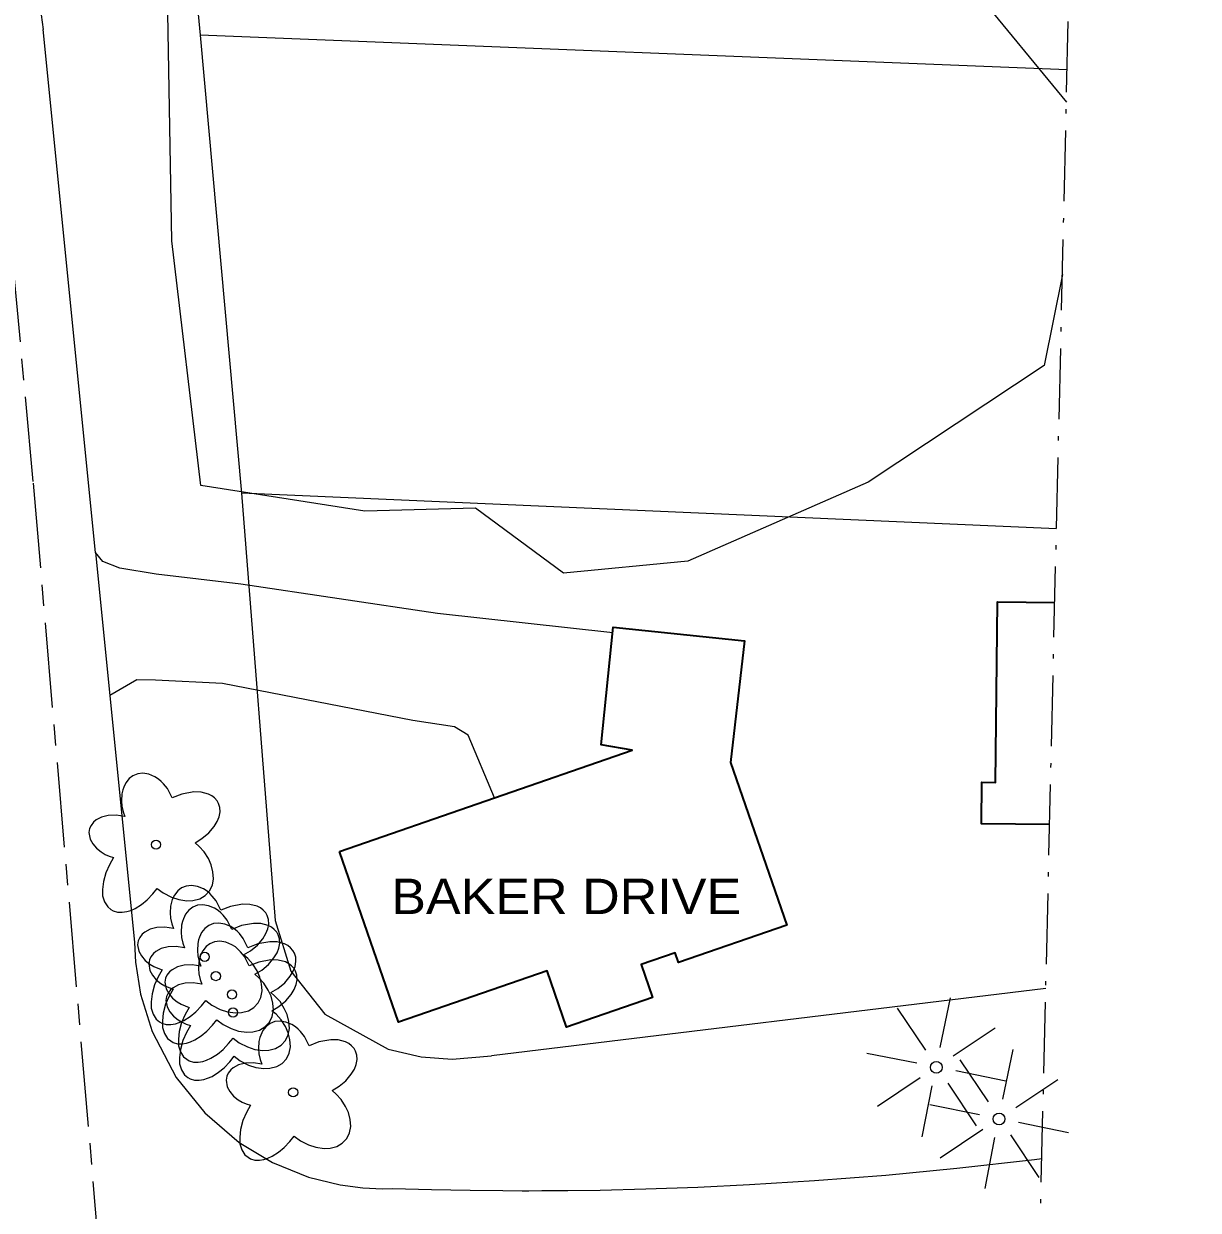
# Model space of a CAD drawing. Extents: x -861682 to -858969, y -1797841 to -1795153.
# Drawn here: x -859173.6 to -858974.4, y -1796344.2 to -1796143 of the extents above; entities that cross this region are included whole.
import ezdxf

# ---------------------------------------------------------------- set-up
doc = ezdxf.new("R2010")
doc.units = 0
doc.header["$LTSCALE"] = 2.4
doc.linetypes.add('DOT_DASHED', pattern=[7.7, 5, -1.2, 0.3, -1.2])
doc.linetypes.add('LONG_DASH_SHORT_DASH', pattern=[9.9, 6, -1.2, 1.5, -1.2])
for name, color, linetype, lineweight in [('10', 7, 'Continuous', 25), ('11', 7, 'Continuous', 13), ('12', 7, 'Continuous', 35), ('17', 7, 'Continuous', 13), ('18', 7, 'Continuous', 13), ('30', 7, 'Continuous', 13), ('32', 7, 'LONG_DASH_SHORT_DASH', 13), ('42', 7, 'Continuous', 25), ('46', 7, 'Continuous', 13), ('61', 7, 'Continuous', 13)]:
    doc.layers.add(name, color=color, linetype=linetype, lineweight=lineweight)

msp = doc.modelspace()

# ---------------------------------------------------------------- linework, layer by layer
at = {"layer": '10'}
for p, q in [((-859161.47, -1796232.698), (-859170.355, -1796144.002)), ((-859161.47, -1796232.698), (-859159.043, -1796256.938)), ((-859159.043, -1796256.938), (-859154.849, -1796298.818))]:
    msp.add_line(p, q, dxfattribs=at)
for points in [[(-859180.121, -1796063.829), (-859178.218, -1796080.987), (-859171.015, -1796139.046), (-859170.355, -1796144.002)], [(-859154.849, -1796298.818), (-859154.675, -1796302.118), (-859153.815, -1796307.556), (-859151.861, -1796313.866), (-859147.776, -1796321.661), (-859142.944, -1796327.66), (-859137.104, -1796332.683), (-859131.441, -1796336.084), (-859125.319, -1796338.563), (-859119.972, -1796339.878), (-859116.105, -1796340.384), (-859112.803, -1796340.532), (-859111.109, -1796340.507)], [(-859111.109, -1796340.507), (-859104.5, -1796340.688), (-859097.889, -1796340.807), (-859092.379, -1796340.859), (-859089.073, -1796340.869), (-859087.971, -1796340.869), (-859085.767, -1796340.864), (-859081.359, -1796340.832), (-859075.85, -1796340.755), (-859068.138, -1796340.573), (-859059.328, -1796340.263), (-859050.522, -1796339.842), (-859039.523, -1796339.161), (-859027.438, -1796338.213), (-859015.372, -1796337.057), (-859002.233, -1796335.559), (-859000.959, -1796335.391)]]:
    msp.add_lwpolyline(points, dxfattribs=at)
at = {"layer": '11'}
for points in [[(-859073.737, -1796246.291), (-859103.483, -1796243.036), (-859136.793, -1796238.058), (-859151.172, -1796236.33), (-859157.333, -1796235.314), (-859160.187, -1796234.203), (-859161.47, -1796232.698)], [(-859093.814, -1796274.266), (-859098.255, -1796263.641), (-859100.565, -1796262.245), (-859107.636, -1796261.142), (-859139.924, -1796254.887), (-859151.276, -1796254.315), (-859154.469, -1796254.239), (-859159.043, -1796256.938)]]:
    msp.add_lwpolyline(points, dxfattribs=at)
at = {"layer": '12'}
msp.add_lwpolyline([(-858999.641, -1796278.809), (-859011.206, -1796278.682), (-859011.128, -1796271.62), (-859008.796, -1796271.646), (-859008.455, -1796241.055), (-858998.765, -1796241.163)], dxfattribs=at)
msp.add_lwpolyline([(-859120.065, -1796283.342), (-859070.464, -1796266.193), (-859075.682, -1796265.265), (-859073.641, -1796245.352), (-859051.384, -1796247.633), (-859053.765, -1796268.256), (-859044.226, -1796295.846), (-859062.594, -1796302.197), (-859063.165, -1796300.545), (-859068.938, -1796302.54), (-859067.011, -1796308.115), (-859081.555, -1796313.142), (-859084.848, -1796303.616), (-859110.046, -1796312.326)], close=True, dxfattribs=at)
at = {"layer": '17'}
for p, q in [((-859018.2, -1796316.6), (-859016.474, -1796308.2)), ((-859020.66, -1796317.06), (-859025.45, -1796309.932)), ((-859016, -1796318), (-859008.904, -1796313.26)), ((-859022.16, -1796319.26), (-859030.622, -1796317.586)), ((-859007.558, -1796325.355), (-859005.832, -1796316.955)), ((-859010.018, -1796325.815), (-859014.808, -1796318.687)), ((-859021.62, -1796321.76), (-859028.846, -1796326.616)), ((-859015.56, -1796320.52), (-859007.08, -1796322.244)), ((-859005.358, -1796326.755), (-858998.262, -1796322.015)), ((-859021.24, -1796331.72), (-859019.56, -1796323.12)), ((-859016.9, -1796322.66), (-859012.1, -1796329.874)), ((-859011.518, -1796328.015), (-859019.98, -1796326.341)), ((-859004.918, -1796329.275), (-858996.438, -1796330.999)), ((-859010.978, -1796330.515), (-859018.204, -1796335.371)), ((-859010.598, -1796340.475), (-859008.918, -1796331.875)), ((-859006.258, -1796331.415), (-859001.458, -1796338.629))]:
    msp.add_line(p, q, dxfattribs=at)
for points in [[(-859151.011, -1796289.617), (-859149.969, -1796290.385), (-859148.563, -1796291.107), (-859147.315, -1796291.513), (-859145.943, -1796291.709), (-859144.925, -1796291.659), (-859143.781, -1796291.369), (-859142.849, -1796290.817), (-859142.109, -1796290.029), (-859141.641, -1796289.071), (-859141.431, -1796287.993), (-859141.535, -1796286.797), (-859141.825, -1796285.625), (-859142.311, -1796284.565), (-859143.033, -1796283.421), (-859143.899, -1796282.501), (-859144.581, -1796281.889), (-859143.399, -1796281.173), (-859142.253, -1796280.225), (-859141.333, -1796279.133), (-859140.811, -1796278.277), (-859140.479, -1796277.463), (-859140.333, -1796276.647), (-859140.373, -1796275.885), (-859140.589, -1796275.205), (-859140.847, -1796274.753), (-859141.267, -1796274.279), (-859141.727, -1796273.925), (-859142.293, -1796273.635), (-859143.529, -1796273.307), (-859144.771, -1796273.273), (-859146.817, -1796273.649), (-859148.477, -1796274.287), (-859149.267, -1796272.709), (-859149.921, -1796271.895), (-859150.333, -1796271.493), (-859150.797, -1796271.093), (-859151.399, -1796270.701), (-859152.403, -1796270.269), (-859153.417, -1796270.099), (-859154.305, -1796270.199), (-859155.105, -1796270.533), (-859155.771, -1796271.019), (-859156.331, -1796271.725), (-859156.681, -1796272.481), (-859156.839, -1796272.919), (-859157.007, -1796273.595), (-859157.059, -1796274.757), (-859156.987, -1796275.655), (-859156.775, -1796276.617), (-859156.491, -1796277.423), (-859157.933, -1796277.191), (-859159.291, -1796277.241), (-859160.449, -1796277.527), (-859161.337, -1796278.025), (-859161.777, -1796278.369), (-859162.211, -1796278.935), (-859162.449, -1796279.469), (-859162.573, -1796280.147), (-859162.371, -1796281.251), (-859161.915, -1796282.063), (-859161.291, -1796282.825), (-859160.513, -1796283.441), (-859159.815, -1796283.865), (-859159.151, -1796284.153), (-859158.423, -1796284.391), (-859159.107, -1796285.603), (-859159.729, -1796286.971), (-859160.125, -1796288.473), (-859160.259, -1796289.807), (-859160.249, -1796290.897), (-859159.915, -1796291.915), (-859159.393, -1796292.761), (-859158.835, -1796293.197), (-859158.449, -1796293.443), (-859157.715, -1796293.667), (-859156.921, -1796293.679), (-859156.151, -1796293.555), (-859155.491, -1796293.343), (-859154.747, -1796293.021), (-859153.671, -1796292.341), (-859152.709, -1796291.555), (-859151.753, -1796290.537), (-859151.007, -1796289.627)], [(-859142.762, -1796308.637), (-859141.72, -1796309.405), (-859140.314, -1796310.127), (-859139.066, -1796310.533), (-859137.694, -1796310.729), (-859136.676, -1796310.679), (-859135.532, -1796310.389), (-859134.6, -1796309.837), (-859133.86, -1796309.049), (-859133.392, -1796308.091), (-859133.182, -1796307.013), (-859133.286, -1796305.817), (-859133.576, -1796304.645), (-859134.062, -1796303.585), (-859134.784, -1796302.441), (-859135.65, -1796301.521), (-859136.332, -1796300.909), (-859135.15, -1796300.193), (-859134.004, -1796299.245), (-859133.084, -1796298.153), (-859132.562, -1796297.297), (-859132.23, -1796296.483), (-859132.084, -1796295.667), (-859132.124, -1796294.905), (-859132.34, -1796294.225), (-859132.598, -1796293.773), (-859133.018, -1796293.299), (-859133.478, -1796292.945), (-859134.044, -1796292.655), (-859135.28, -1796292.327), (-859136.522, -1796292.293), (-859138.568, -1796292.669), (-859140.228, -1796293.307), (-859141.018, -1796291.729), (-859141.672, -1796290.915), (-859142.084, -1796290.513), (-859142.548, -1796290.113), (-859143.15, -1796289.721), (-859144.154, -1796289.289), (-859145.168, -1796289.119), (-859146.056, -1796289.219), (-859146.856, -1796289.553), (-859147.522, -1796290.039), (-859148.082, -1796290.745), (-859148.432, -1796291.501), (-859148.59, -1796291.939), (-859148.758, -1796292.615), (-859148.81, -1796293.777), (-859148.738, -1796294.675), (-859148.526, -1796295.637), (-859148.242, -1796296.443), (-859149.684, -1796296.211), (-859151.042, -1796296.261), (-859152.2, -1796296.547), (-859153.088, -1796297.045), (-859153.528, -1796297.389), (-859153.962, -1796297.955), (-859154.2, -1796298.489), (-859154.324, -1796299.167), (-859154.122, -1796300.271), (-859153.666, -1796301.083), (-859153.042, -1796301.845), (-859152.264, -1796302.461), (-859151.566, -1796302.885), (-859150.902, -1796303.173), (-859150.174, -1796303.411), (-859150.858, -1796304.623), (-859151.48, -1796305.991), (-859151.876, -1796307.493), (-859152.01, -1796308.827), (-859152, -1796309.917), (-859151.666, -1796310.935), (-859151.144, -1796311.781), (-859150.586, -1796312.217), (-859150.2, -1796312.463), (-859149.466, -1796312.687), (-859148.672, -1796312.699), (-859147.902, -1796312.575), (-859147.242, -1796312.363), (-859146.498, -1796312.041), (-859145.422, -1796311.361), (-859144.46, -1796310.575), (-859143.504, -1796309.557), (-859142.758, -1796308.647)], [(-859140.874, -1796311.906), (-859139.832, -1796312.674), (-859138.426, -1796313.396), (-859137.178, -1796313.802), (-859135.806, -1796313.998), (-859134.788, -1796313.948), (-859133.644, -1796313.658), (-859132.712, -1796313.106), (-859131.972, -1796312.318), (-859131.504, -1796311.36), (-859131.294, -1796310.282), (-859131.398, -1796309.086), (-859131.688, -1796307.914), (-859132.174, -1796306.854), (-859132.896, -1796305.71), (-859133.762, -1796304.79), (-859134.444, -1796304.178), (-859133.262, -1796303.462), (-859132.116, -1796302.514), (-859131.196, -1796301.422), (-859130.674, -1796300.566), (-859130.342, -1796299.752), (-859130.196, -1796298.936), (-859130.236, -1796298.174), (-859130.452, -1796297.494), (-859130.71, -1796297.042), (-859131.13, -1796296.568), (-859131.59, -1796296.214), (-859132.156, -1796295.924), (-859133.392, -1796295.596), (-859134.634, -1796295.562), (-859136.68, -1796295.938), (-859138.34, -1796296.576), (-859139.13, -1796294.998), (-859139.784, -1796294.184), (-859140.196, -1796293.782), (-859140.66, -1796293.382), (-859141.262, -1796292.99), (-859142.266, -1796292.558), (-859143.28, -1796292.388), (-859144.168, -1796292.488), (-859144.968, -1796292.822), (-859145.634, -1796293.308), (-859146.194, -1796294.014), (-859146.544, -1796294.77), (-859146.702, -1796295.208), (-859146.87, -1796295.884), (-859146.922, -1796297.046), (-859146.85, -1796297.944), (-859146.638, -1796298.906), (-859146.354, -1796299.712), (-859147.796, -1796299.48), (-859149.154, -1796299.53), (-859150.312, -1796299.816), (-859151.2, -1796300.314), (-859151.64, -1796300.658), (-859152.074, -1796301.224), (-859152.312, -1796301.758), (-859152.436, -1796302.436), (-859152.234, -1796303.54), (-859151.778, -1796304.352), (-859151.154, -1796305.114), (-859150.376, -1796305.73), (-859149.678, -1796306.154), (-859149.014, -1796306.442), (-859148.286, -1796306.68), (-859148.97, -1796307.892), (-859149.592, -1796309.26), (-859149.988, -1796310.762), (-859150.122, -1796312.096), (-859150.112, -1796313.186), (-859149.778, -1796314.204), (-859149.256, -1796315.05), (-859148.698, -1796315.486), (-859148.312, -1796315.732), (-859147.578, -1796315.956), (-859146.784, -1796315.968), (-859146.014, -1796315.844), (-859145.354, -1796315.632), (-859144.61, -1796315.31), (-859143.534, -1796314.63), (-859142.572, -1796313.844), (-859141.616, -1796312.826), (-859140.87, -1796311.916)], [(-859138.134, -1796315.013), (-859137.092, -1796315.781), (-859135.686, -1796316.503), (-859134.438, -1796316.909), (-859133.066, -1796317.105), (-859132.048, -1796317.055), (-859130.904, -1796316.765), (-859129.972, -1796316.213), (-859129.232, -1796315.425), (-859128.764, -1796314.467), (-859128.554, -1796313.389), (-859128.658, -1796312.193), (-859128.948, -1796311.021), (-859129.434, -1796309.961), (-859130.156, -1796308.817), (-859131.022, -1796307.897), (-859131.704, -1796307.285), (-859130.522, -1796306.569), (-859129.376, -1796305.621), (-859128.456, -1796304.529), (-859127.934, -1796303.673), (-859127.602, -1796302.859), (-859127.456, -1796302.043), (-859127.496, -1796301.281), (-859127.712, -1796300.601), (-859127.97, -1796300.149), (-859128.39, -1796299.675), (-859128.85, -1796299.321), (-859129.416, -1796299.031), (-859130.652, -1796298.703), (-859131.894, -1796298.669), (-859133.94, -1796299.045), (-859135.6, -1796299.683), (-859136.39, -1796298.105), (-859137.044, -1796297.291), (-859137.456, -1796296.889), (-859137.92, -1796296.489), (-859138.522, -1796296.097), (-859139.526, -1796295.665), (-859140.54, -1796295.495), (-859141.428, -1796295.595), (-859142.228, -1796295.929), (-859142.894, -1796296.415), (-859143.454, -1796297.121), (-859143.804, -1796297.877), (-859143.962, -1796298.315), (-859144.13, -1796298.991), (-859144.182, -1796300.153), (-859144.11, -1796301.051), (-859143.898, -1796302.013), (-859143.614, -1796302.819), (-859145.056, -1796302.587), (-859146.414, -1796302.637), (-859147.572, -1796302.923), (-859148.46, -1796303.421), (-859148.9, -1796303.765), (-859149.334, -1796304.331), (-859149.572, -1796304.865), (-859149.696, -1796305.543), (-859149.494, -1796306.647), (-859149.038, -1796307.459), (-859148.414, -1796308.221), (-859147.636, -1796308.837), (-859146.938, -1796309.261), (-859146.274, -1796309.549), (-859145.546, -1796309.787), (-859146.23, -1796310.999), (-859146.852, -1796312.367), (-859147.248, -1796313.869), (-859147.382, -1796315.203), (-859147.372, -1796316.293), (-859147.038, -1796317.311), (-859146.516, -1796318.157), (-859145.958, -1796318.593), (-859145.572, -1796318.839), (-859144.838, -1796319.063), (-859144.044, -1796319.075), (-859143.274, -1796318.951), (-859142.614, -1796318.739), (-859141.87, -1796318.417), (-859140.794, -1796317.737), (-859139.832, -1796316.951), (-859138.876, -1796315.933), (-859138.13, -1796315.023)], [(-859137.956, -1796318.08), (-859136.914, -1796318.848), (-859135.508, -1796319.57), (-859134.26, -1796319.976), (-859132.888, -1796320.172), (-859131.87, -1796320.122), (-859130.726, -1796319.832), (-859129.794, -1796319.28), (-859129.054, -1796318.492), (-859128.586, -1796317.534), (-859128.376, -1796316.456), (-859128.48, -1796315.26), (-859128.77, -1796314.088), (-859129.256, -1796313.028), (-859129.978, -1796311.884), (-859130.844, -1796310.964), (-859131.526, -1796310.352), (-859130.344, -1796309.636), (-859129.198, -1796308.688), (-859128.278, -1796307.596), (-859127.756, -1796306.74), (-859127.424, -1796305.926), (-859127.278, -1796305.11), (-859127.318, -1796304.348), (-859127.534, -1796303.668), (-859127.792, -1796303.216), (-859128.212, -1796302.742), (-859128.672, -1796302.388), (-859129.238, -1796302.098), (-859130.474, -1796301.77), (-859131.716, -1796301.736), (-859133.762, -1796302.112), (-859135.422, -1796302.75), (-859136.212, -1796301.172), (-859136.866, -1796300.358), (-859137.278, -1796299.956), (-859137.742, -1796299.556), (-859138.344, -1796299.164), (-859139.348, -1796298.732), (-859140.362, -1796298.562), (-859141.25, -1796298.662), (-859142.05, -1796298.996), (-859142.716, -1796299.482), (-859143.276, -1796300.188), (-859143.626, -1796300.944), (-859143.784, -1796301.382), (-859143.952, -1796302.058), (-859144.004, -1796303.22), (-859143.932, -1796304.118), (-859143.72, -1796305.08), (-859143.436, -1796305.886), (-859144.878, -1796305.654), (-859146.236, -1796305.704), (-859147.394, -1796305.99), (-859148.282, -1796306.488), (-859148.722, -1796306.832), (-859149.156, -1796307.398), (-859149.394, -1796307.932), (-859149.518, -1796308.61), (-859149.316, -1796309.714), (-859148.86, -1796310.526), (-859148.236, -1796311.288), (-859147.458, -1796311.904), (-859146.76, -1796312.328), (-859146.096, -1796312.616), (-859145.368, -1796312.854), (-859146.052, -1796314.066), (-859146.674, -1796315.434), (-859147.07, -1796316.936), (-859147.204, -1796318.27), (-859147.194, -1796319.36), (-859146.86, -1796320.378), (-859146.338, -1796321.224), (-859145.78, -1796321.66), (-859145.394, -1796321.906), (-859144.66, -1796322.13), (-859143.866, -1796322.142), (-859143.096, -1796322.018), (-859142.436, -1796321.806), (-859141.692, -1796321.484), (-859140.616, -1796320.804), (-859139.654, -1796320.018), (-859138.698, -1796319), (-859137.952, -1796318.09)], [(-859127.76, -1796331.623), (-859126.718, -1796332.391), (-859125.312, -1796333.113), (-859124.064, -1796333.519), (-859122.692, -1796333.715), (-859121.674, -1796333.665), (-859120.53, -1796333.375), (-859119.598, -1796332.823), (-859118.858, -1796332.035), (-859118.39, -1796331.077), (-859118.18, -1796329.999), (-859118.284, -1796328.803), (-859118.574, -1796327.631), (-859119.06, -1796326.571), (-859119.782, -1796325.427), (-859120.648, -1796324.507), (-859121.33, -1796323.895), (-859120.148, -1796323.179), (-859119.002, -1796322.231), (-859118.082, -1796321.139), (-859117.56, -1796320.283), (-859117.228, -1796319.469), (-859117.082, -1796318.653), (-859117.122, -1796317.891), (-859117.338, -1796317.211), (-859117.596, -1796316.759), (-859118.016, -1796316.285), (-859118.476, -1796315.931), (-859119.042, -1796315.641), (-859120.278, -1796315.313), (-859121.52, -1796315.279), (-859123.566, -1796315.655), (-859125.226, -1796316.293), (-859126.016, -1796314.715), (-859126.67, -1796313.901), (-859127.082, -1796313.499), (-859127.546, -1796313.099), (-859128.148, -1796312.707), (-859129.152, -1796312.275), (-859130.166, -1796312.105), (-859131.054, -1796312.205), (-859131.854, -1796312.539), (-859132.52, -1796313.025), (-859133.08, -1796313.731), (-859133.43, -1796314.487), (-859133.588, -1796314.925), (-859133.756, -1796315.601), (-859133.808, -1796316.763), (-859133.736, -1796317.661), (-859133.524, -1796318.623), (-859133.24, -1796319.429), (-859134.682, -1796319.197), (-859136.04, -1796319.247), (-859137.198, -1796319.533), (-859138.086, -1796320.031), (-859138.526, -1796320.375), (-859138.96, -1796320.941), (-859139.198, -1796321.475), (-859139.322, -1796322.153), (-859139.12, -1796323.257), (-859138.664, -1796324.069), (-859138.04, -1796324.831), (-859137.262, -1796325.447), (-859136.564, -1796325.871), (-859135.9, -1796326.159), (-859135.172, -1796326.397), (-859135.856, -1796327.609), (-859136.478, -1796328.977), (-859136.874, -1796330.479), (-859137.008, -1796331.813), (-859136.998, -1796332.903), (-859136.664, -1796333.921), (-859136.142, -1796334.767), (-859135.584, -1796335.203), (-859135.198, -1796335.449), (-859134.464, -1796335.673), (-859133.67, -1796335.685), (-859132.9, -1796335.561), (-859132.24, -1796335.349), (-859131.496, -1796335.027), (-859130.42, -1796334.347), (-859129.458, -1796333.561), (-859128.502, -1796332.543), (-859127.756, -1796331.633)]]:
    msp.add_lwpolyline(points, dxfattribs=at)
for centre, radius in [((-859151.191, -1796282.205), 0.773), ((-859142.942, -1796301.225), 0.773), ((-859141.054, -1796304.494), 0.773), ((-859138.314, -1796307.601), 0.773), ((-859138.136, -1796310.668), 0.773), ((-859018.86, -1796319.96), 1), ((-859127.94, -1796324.211), 0.773), ((-859008.218, -1796328.715), 1)]:
    msp.add_circle(centre, radius, dxfattribs=at)
at = {"layer": '18'}
msp.add_line((-858997.47, -1796185.563), (-859000.584, -1796200.948), dxfattribs=at)
msp.add_lwpolyline([(-859000.584, -1796200.948), (-859030.413, -1796220.763), (-859061.004, -1796234.175), (-859082.06, -1796236.181), (-859097.001, -1796225.145), (-859115.759, -1796225.664), (-859143.622, -1796221.311), (-859148.513, -1796179.853), (-859149.493, -1796125.159), (-859163.095, -1796083.032), (-859153.599, -1796072.325), (-859106.129, -1796073.572), (-859073.857, -1796095.639), (-859070.132, -1796112.997), (-859043.544, -1796120.651), (-859012.341, -1796137.386), (-858996.789, -1796156.325)], dxfattribs=at)
at = {"layer": '30'}
for p, q in [((-858996.661, -1796150.826), (-859143.732, -1796144.99)), ((-858998.474, -1796228.675), (-859136.702, -1796222.627))]:
    msp.add_line(p, q, dxfattribs=at)
at = {"layer": '32'}
msp.add_lwpolyline([(-859608.727, -1795645.905), (-859547.475, -1795663.972), (-859512.218, -1795672.548), (-859448.852, -1795685.888), (-859390.25, -1795702.087), (-859346.418, -1795718.286), (-859312.114, -1795735.914), (-859284.005, -1795754.971), (-859271.617, -1795770.217), (-859251.13, -1795810.238), (-859242.554, -1795833.584), (-859228.738, -1795871.699), (-859218.732, -1795901.238), (-859209.68, -1795935.065), (-859202.057, -1795970.321), (-859196.34, -1796004.625), (-859192.528, -1796042.264), (-859177.759, -1796158.991), (-859172.04, -1796220.929), (-859156.019, -1796407.84)], dxfattribs=at)
at = {"layer": '42'}
msp.add_line((-859000.289, -1796306.601), (-859094.272, -1796318.009), dxfattribs=at)
for points in [[(-859152.648, -1796051.454), (-859143.732, -1796144.99), (-859136.702, -1796222.627), (-859130.98, -1796295.086)], [(-859130.98, -1796295.086), (-859128.35, -1796303.674), (-859122.57, -1796310.918), (-859111.827, -1796316.9), (-859106.21, -1796318.205), (-859100.962, -1796318.596), (-859094.272, -1796318.009)]]:
    msp.add_lwpolyline(points, dxfattribs=at)
at = {"layer": '61', "linetype": 'DOT_DASHED'}
msp.add_line((-859035.9, -1797835.881), (-858974.429, -1795196.105), dxfattribs=at)

# ---------------------------------------------------------------- texts
at = {"layer": '46', "width": 1.1}
msp.add_text('BAKER DRIVE', height=6, dxfattribs=at).set_placement((-859111.3, -1796293.978))

doc.saveas('drawing.dxf')
